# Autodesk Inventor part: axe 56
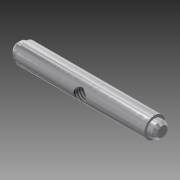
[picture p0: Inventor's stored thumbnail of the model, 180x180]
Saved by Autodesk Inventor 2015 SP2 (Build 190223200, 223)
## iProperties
Created: 2015-08
Part Number: axe 56
Material: Générique
Document SubType Name: Modeling
Designer: Dominique
Density: 1 g/cm^3
Appearance: Usiné - Aluminium
Author: Dominique
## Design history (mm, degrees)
sketch "Esquisse1"
  geometry: L1 (0, 0)-(56, 0); L2 (56, 0)-(56, 3); L3 (53, 4)-(3, 4); L4 (0, 3)-(0, 0); L5 (3, 4)-(3, 3); L6 (3, 3)-(0, 3); L7 (53, 4)-(53, 3); L8 (53, 3)-(56, 3)
  constraints: 16 end point, 2 parallel, 1 horizontal, 1 perpendicular
revolve "Révolution1" sketch "Esquisse1" stored, may be unused: angle "d6" = 90 deg
chamfer "Chanfrein1" distance "d7" = 1; stored, may be unused: second distance "d8" = 2, angle "d9" = 45 deg
sketch "Esquisse3"
  geometry: L1 (-3, 4)-(-53, 4) reference; L2 (-28, 4)-(-28, 0); C1 r 2.5 at (-28, 0); 1 further point
  constraints: 2 end point, 1 centre point, 1 coincident, 1 midpoint, 1 vertical
  dimensions: "d26" = 5 diameter of C1
extrude "Extrusion1" cut sketch "Esquisse3" stored distance "d27" = 10; taper "d28" = 0 deg
feature "Filetage1" dims "d29" = 10, "d30" = 0
node "Solide1"
